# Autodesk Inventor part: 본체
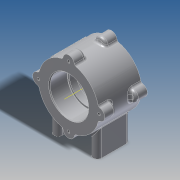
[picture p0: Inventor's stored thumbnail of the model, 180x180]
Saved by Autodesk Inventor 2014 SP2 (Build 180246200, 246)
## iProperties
Created: 2015-03
Part Number: 본체
Material: 알루미늄 6061
Document SubType Name: Modeling
Designer: 201-07
Mass: 448.938 g
Surface Area: 330.888 cm^2
Volume: 165.66 cm^3
Density: 2.71 g/cm^3
Appearance: 알루미늄 - 평지
Author: 201-07
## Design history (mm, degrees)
sketch "스케치1"
  geometry: C1 r 37 at (0, 0); 1 further point
  constraints: 1 centre point, 1 coincident
  dimensions: "d0" = 74 diameter of C1
extrude "돌출1" new body sketch "스케치1" stored distance "d1" = 52; taper "d2" = 0 deg
sketch "스케치2"
  geometry: C1 r 7 at (0, 37); 1 further point
  constraints: 2 vertical alignment, 1 centre point, 1 other
  dimensions: "d3" = 14 diameter of C1
extrude "돌출2" join sketch "스케치2" distance "d4" = 14; taper "d5" = 0 deg
fillet "모깎기1" dims "d6" = 3
sketch "스케치3"
  geometry: L1 (-29, -14.37)-(-19, -14.37); L2 (-19, -14.37)-(-19, -56); L3 (-19, -56)-(-29, -56); L4 (-29, -56)-(-29, -14.37); L5 (-24, -56)-(-24, -14.37); 1 further point
  constraints: 10 end point, 2 midpoint, 2 parallel, 1 horizontal, 1 perpendicular
  dimensions: "d10" = 56 distance from line of L3 point (0, 0); "d11" = 10 distance of L2.end L3.end; "d12" = 24 horizontal distance of L5.start point (0, 0)
extrude "돌출3" join sketch "스케치3" stored distance "d13" = 40; taper "d14" = 0 deg
fillet "모깎기2" dims "d15" = 5
fillet "모깎기3" dims "d16" = 3
sketch "스케치4"
  geometry: A1 r 5 centre (0, 0) between (-5, 0) and (5, 0) reference; A2 r 5 centre (0, 30) between (5, 30) and (-5, 30) reference; 1 further point
hole "구멍1" sketch "스케치4" at (0, 30), (0, 0) diameter "d17" = 4.134; stored, may be unused: countersink angle "d21" = 82 deg, drill point angle "d23" = 118 deg; dims "d18" = 6, "d19" = 3.023, "d20" = 2, "d22" = 8
sketch "스케치5"
  geometry: A1 r 7 centre (0, 37) between (6.889, 38.239) and (-6.889, 38.239) reference; A2 r 7 centre (-37, 0) between (-38.239, 6.889) and (-38.239, -6.889) reference; A3 r 7 centre (0, -37) between (-6.889, -38.239) and (6.889, -38.239) reference; A4 r 7 centre (37, 0) between (38.239, -6.889) and (38.239, 6.889) reference
hole "구멍2" sketch "스케치5" at (0, 37), (-37, 0), (37, 0), (0, -37) diameter "d24" = 3.242; stored, may be unused: countersink angle "d28" = 82 deg, drill point angle "d30" = 118 deg; dims "d25" = 8, "d26" = 3.023, "d27" = 2, "d29" = 11
hole "구멍3" diameter "d33" = 42; stored, may be unused: countersink angle "d37" = 82 deg, drill point angle "d39" = 0 deg; dims "d34" = 8, "d35" = 3.023, "d36" = 2, "d38" = 11, "d42" = 10, "d43" = 10
hole "구멍4" diameter "d44" = 47; stored, may be unused: countersink angle "d48" = 82 deg, drill point angle "d50" = 0 deg; dims "d40" = 10, "d41" = 10, "d45" = 8, "d46" = 3.023, "d47" = 2, "d49" = 22
hole "구멍5" diameter "d53" = 47; stored, may be unused: countersink angle "d57" = 82 deg, drill point angle "d59" = 0 deg; dims "d51" = 10, "d52" = 10, "d54" = 8, "d55" = 3.023, "d56" = 2, "d58" = 22
fillet "모깎기4" dims "d60" = 0.3
chamfer "모따기1" distance "d61" = 1; stored, may be unused: second distance "d62" = 2, angle "d63" = 45 deg
node "작업 평면3"
  node "작업 평면2"
sketch "스케치6"
  geometry: L1 (-3.002, -20.739)-(-3.002, 20.739); L2 (-3.002, 20.739)-(3.002, 20.739); L3 (3.002, 20.739)-(3.002, -20.739); L4 (3.002, -20.739)-(-3.002, -20.739); 3 further points
  constraints: 2 midpoint, 1 horizontal alignment, 1 vertical alignment, 2 other
feature "엠보싱1" sketch "스케치6" dims "d65" = 0.5, "d66" = 0
node "솔리드1"
pattern_circular "원형 패턴1" dims angle "d8" = 360 deg
mirror "대칭1"
mirror "대칭2"
mirror "대칭3"
node "작업 평면1"
node "작업축1"
other parameters: "d64" = -45 deg
